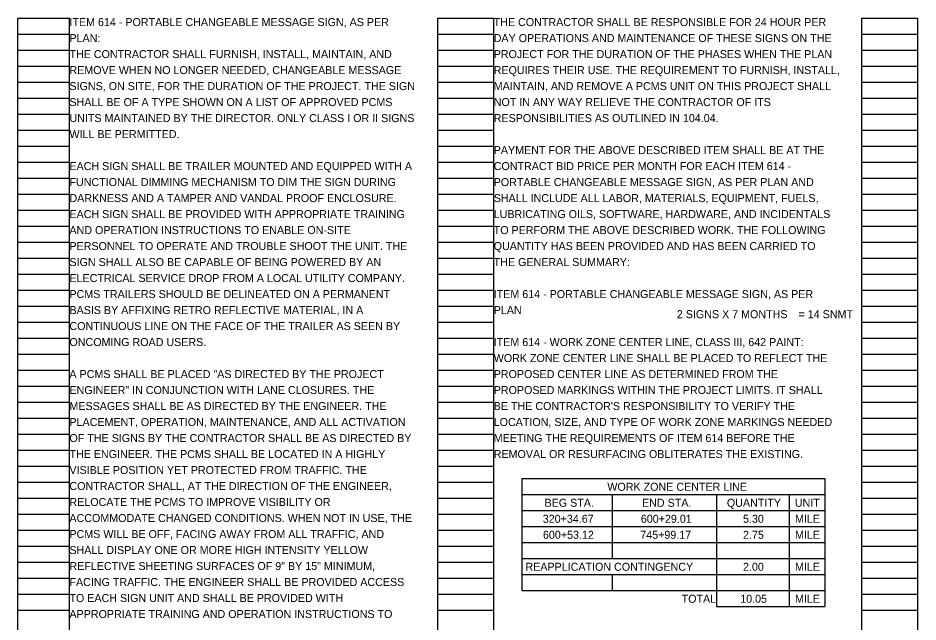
# Model space of a CAD drawing. Extents: x 63 to 145.9, y -75 to 21.1.
# Drawn here: x 64.47 to 80.21, y -39.43 to -28.86 of the extents above; entities that cross this region are included whole.
import ezdxf

# ---------------------------------------------------------------- set-up
doc = ezdxf.new("R2010")
doc.units = 0
doc.layers.add('AP_P_Airside', color=7, linetype='Continuous')
doc.layers.add('SH_Text', color=7, linetype='Continuous')

msp = doc.modelspace()

# ---------------------------------------------------------------- linework, layer by layer
at = {"layer": 'AP_P_Airside'}
for p, q in [((73.275, -36.919), (78.579, -36.919)), ((73.275, -36.919), (73.275, -38.879)), ((78.579, -36.919), (78.579, -39.159)), ((73.275, -37.199), (78.579, -37.199)), ((74.856, -37.199), (74.856, -38.319)), ((76.684, -37.199), (76.684, -39.159)), ((77.953, -37.199), (77.953, -39.159)), ((73.275, -37.479), (78.579, -37.479)), ((73.275, -37.759), (78.579, -37.759)), ((73.275, -38.039), (78.579, -38.039)), ((73.275, -38.319), (78.579, -38.319)), ((73.275, -38.599), (78.579, -38.599)), ((74.856, -38.599), (74.856, -38.879)), ((73.275, -38.879), (78.579, -38.879)), ((76.684, -39.159), (78.579, -39.159))]:
    msp.add_line(p, q, dxfattribs=at)
at = {"layer": 'SH_Text'}
for p, q in [((64.466, -49.02), (64.466, -28.86)), ((64.466, -28.86), (65.366, -28.86)), ((65.366, -49.02), (65.366, -28.86)), ((71.806, -49.02), (71.806, -28.86)), ((71.806, -28.86), (72.786, -28.86)), ((72.786, -49.02), (72.786, -28.86)), ((79.226, -49.02), (79.226, -28.86)), ((79.226, -28.86), (80.206, -28.86)), ((80.206, -49.02), (80.206, -28.86)), ((64.466, -29.14), (65.366, -29.14)), ((71.806, -29.14), (72.786, -29.14)), ((79.226, -29.14), (80.206, -29.14)), ((64.466, -29.42), (65.366, -29.42)), ((71.806, -29.42), (72.786, -29.42)), ((79.226, -29.42), (80.206, -29.42)), ((64.466, -29.7), (65.366, -29.7)), ((71.806, -29.7), (72.786, -29.7)), ((79.226, -29.7), (80.206, -29.7)), ((64.466, -29.98), (65.366, -29.98)), ((71.806, -29.98), (72.786, -29.98)), ((79.226, -29.98), (80.206, -29.98)), ((64.466, -30.26), (65.366, -30.26)), ((71.806, -30.26), (72.786, -30.26)), ((79.226, -30.26), (80.206, -30.26)), ((64.466, -30.54), (65.366, -30.54)), ((71.806, -30.54), (72.786, -30.54)), ((79.226, -30.54), (80.206, -30.54)), ((64.466, -30.82), (65.366, -30.82)), ((71.806, -30.82), (72.786, -30.82)), ((79.226, -30.82), (80.206, -30.82)), ((64.466, -31.1), (65.366, -31.1)), ((71.806, -31.1), (72.786, -31.1)), ((79.226, -31.1), (80.206, -31.1)), ((64.466, -31.38), (65.366, -31.38)), ((71.806, -31.38), (72.786, -31.38)), ((79.226, -31.38), (80.206, -31.38)), ((64.466, -31.66), (65.366, -31.66)), ((71.806, -31.66), (72.786, -31.66)), ((79.226, -31.66), (80.206, -31.66)), ((64.466, -31.94), (65.366, -31.94)), ((71.806, -31.94), (72.786, -31.94)), ((79.226, -31.94), (80.206, -31.94)), ((64.466, -32.22), (65.366, -32.22)), ((71.806, -32.22), (72.786, -32.22)), ((79.226, -32.22), (80.206, -32.22)), ((64.466, -32.5), (65.366, -32.5)), ((71.806, -32.5), (72.786, -32.5)), ((79.226, -32.5), (80.206, -32.5)), ((64.466, -32.78), (65.366, -32.78)), ((71.806, -32.78), (72.786, -32.78)), ((79.226, -32.78), (80.206, -32.78)), ((64.466, -33.06), (65.366, -33.06)), ((71.806, -33.06), (72.786, -33.06)), ((79.226, -33.06), (80.206, -33.06)), ((64.466, -33.34), (65.366, -33.34)), ((71.806, -33.34), (72.786, -33.34)), ((79.226, -33.34), (80.206, -33.34)), ((64.466, -33.62), (65.366, -33.62)), ((71.806, -33.62), (72.786, -33.62)), ((79.226, -33.62), (80.206, -33.62)), ((64.466, -33.9), (65.366, -33.9)), ((71.806, -33.9), (72.786, -33.9)), ((79.226, -33.9), (80.206, -33.9)), ((64.466, -34.18), (65.366, -34.18)), ((71.806, -34.18), (72.786, -34.18)), ((79.226, -34.18), (80.206, -34.18)), ((64.466, -34.46), (65.366, -34.46)), ((71.806, -34.46), (72.786, -34.46)), ((79.226, -34.46), (80.206, -34.46)), ((64.466, -34.74), (65.366, -34.74)), ((71.806, -34.74), (72.786, -34.74)), ((79.226, -34.74), (80.206, -34.74)), ((64.466, -35.02), (65.366, -35.02)), ((71.806, -35.02), (72.786, -35.02)), ((79.226, -35.02), (80.206, -35.02)), ((64.466, -35.3), (65.366, -35.3)), ((71.806, -35.3), (72.786, -35.3)), ((79.226, -35.3), (80.206, -35.3)), ((64.466, -35.58), (65.366, -35.58)), ((71.806, -35.58), (72.786, -35.58)), ((79.226, -35.58), (80.206, -35.58)), ((64.466, -35.86), (65.366, -35.86)), ((71.806, -35.86), (72.786, -35.86)), ((79.226, -35.86), (80.206, -35.86)), ((64.466, -36.14), (65.366, -36.14)), ((71.806, -36.14), (72.786, -36.14)), ((79.226, -36.14), (80.206, -36.14)), ((64.466, -36.42), (65.366, -36.42)), ((71.806, -36.42), (72.786, -36.42)), ((79.226, -36.42), (80.206, -36.42)), ((64.466, -36.7), (65.366, -36.7)), ((71.806, -36.7), (72.786, -36.7)), ((79.226, -36.7), (80.206, -36.7)), ((64.466, -36.98), (65.366, -36.98)), ((71.806, -36.98), (72.786, -36.98)), ((79.226, -36.98), (80.206, -36.98)), ((64.466, -37.26), (65.366, -37.26)), ((71.806, -37.26), (72.786, -37.26)), ((79.226, -37.26), (80.206, -37.26)), ((64.466, -37.54), (65.366, -37.54)), ((71.806, -37.54), (72.786, -37.54)), ((79.226, -37.54), (80.206, -37.54)), ((64.466, -37.82), (65.366, -37.82)), ((71.806, -37.82), (72.786, -37.82)), ((79.226, -37.82), (80.206, -37.82)), ((64.466, -38.1), (65.366, -38.1)), ((71.806, -38.1), (72.786, -38.1)), ((79.226, -38.1), (80.206, -38.1)), ((64.466, -38.38), (65.366, -38.38)), ((71.806, -38.38), (72.786, -38.38)), ((79.226, -38.38), (80.206, -38.38)), ((64.466, -38.66), (65.366, -38.66)), ((71.806, -38.66), (72.786, -38.66)), ((79.226, -38.66), (80.206, -38.66)), ((64.466, -38.94), (65.366, -38.94)), ((71.806, -38.94), (72.786, -38.94)), ((79.226, -38.94), (80.206, -38.94)), ((64.466, -39.22), (65.366, -39.22)), ((71.806, -39.22), (72.786, -39.22)), ((79.226, -39.22), (80.206, -39.22))]:
    msp.add_line(p, q, dxfattribs=at)

# ---------------------------------------------------------------- texts
at = {"layer": 'AP_P_Airside'}
for s, p in [('ITEM 614 - PORTABLE CHANGEABLE MESSAGE SIGN, AS PER ', (65.366, -29)), ('THE CONTRACTOR SHALL BE RESPONSIBLE FOR 24 HOUR PER ', (72.786, -29)), ('PLAN:', (65.366, -29.28)), ('DAY OPERATIONS AND MAINTENANCE OF THESE SIGNS ON THE ', (72.786, -29.28)), ('THE CONTRACTOR SHALL FURNISH, INSTALL, MAINTAIN, AND ', (65.366, -29.56)), ('PROJECT FOR THE DURATION OF THE PHASES WHEN THE PLAN ', (72.786, -29.56)), ('REMOVE WHEN NO LONGER NEEDED, CHANGEABLE MESSAGE ', (65.366, -29.84)), ('REQUIRES THEIR USE. THE REQUIREMENT TO FURNISH, INSTALL, ', (72.786, -29.84)), ('SIGNS, ON SITE, FOR THE DURATION OF THE PROJECT. THE SIGN ', (65.366, -30.12)), ('MAINTAIN, AND REMOVE A PCMS UNIT ON THIS PROJECT SHALL ', (72.786, -30.12)), ('SHALL BE OF A TYPE SHOWN ON A LIST OF APPROVED PCMS ', (65.366, -30.4)), ('NOT IN ANY WAY RELIEVE THE CONTRACTOR OF ITS ', (72.786, -30.4)), ('UNITS MAINTAINED BY THE DIRECTOR. ONLY CLASS I OR II SIGNS ', (65.366, -30.68)), ('RESPONSIBILITIES AS OUTLINED IN 104.04.', (72.786, -30.68)), ('WILL BE PERMITTED.', (65.366, -30.96)), ('PAYMENT FOR THE ABOVE DESCRIBED ITEM SHALL BE AT THE ', (72.786, -31.24)), ('EACH SIGN SHALL BE TRAILER MOUNTED AND EQUIPPED WITH A ', (65.366, -31.52)), ('CONTRACT BID PRICE PER MONTH FOR EACH ITEM 614 - ', (72.786, -31.52)), ('FUNCTIONAL DIMMING MECHANISM TO DIM THE SIGN DURING ', (65.366, -31.8)), ('PORTABLE CHANGEABLE MESSAGE SIGN, AS PER PLAN AND ', (72.786, -31.8)), ('DARKNESS AND A TAMPER AND VANDAL PROOF ENCLOSURE. ', (65.366, -32.08)), ('SHALL INCLUDE ALL LABOR, MATERIALS, EQUIPMENT, FUELS, ', (72.786, -32.08)), ('EACH SIGN SHALL BE PROVIDED WITH APPROPRIATE TRAINING ', (65.366, -32.36)), ('LUBRICATING OILS, SOFTWARE, HARDWARE, AND INCIDENTALS ', (72.786, -32.36)), ('AND OPERATION INSTRUCTIONS TO ENABLE ON-SITE ', (65.366, -32.64)), ('TO PERFORM THE ABOVE DESCRIBED WORK. THE FOLLOWING ', (72.786, -32.64)), ('PERSONNEL TO OPERATE AND TROUBLE SHOOT THE UNIT. THE ', (65.366, -32.92)), ('QUANTITY HAS BEEN PROVIDED AND HAS BEEN CARRIED TO ', (72.786, -32.92)), ('SIGN SHALL ALSO BE CAPABLE OF BEING POWERED BY AN ', (65.366, -33.2)), ('THE GENERAL SUMMARY:', (72.786, -33.2)), ('ELECTRICAL SERVICE DROP FROM A LOCAL UTILITY COMPANY. ', (65.366, -33.48)), ('PCMS TRAILERS SHOULD BE DELINEATED ON A PERMANENT ', (65.366, -33.76)), ('ITEM 614 - PORTABLE CHANGEABLE MESSAGE SIGN, AS PER ', (72.786, -33.76)), ('BASIS BY AFFIXING RETRO REFLECTIVE MATERIAL, IN A ', (65.366, -34.04)), ('PLAN', (72.786, -34.04)), ('2 SIGNS X 7 MONTHS', (75.989, -34.112)), ('= 14 SNMT', (78.117, -34.112)), ('CONTINUOUS LINE ON THE FACE OF THE TRAILER AS SEEN BY ', (65.366, -34.32)), ('ONCOMING ROAD USERS.', (65.366, -34.6)), ('ITEM 614 - WORK ZONE CENTER LINE, CLASS III, 642 PAINT:', (72.786, -34.6)), ('WORK ZONE CENTER LINE SHALL BE PLACED TO REFLECT THE ', (72.786, -34.88)), ('A PCMS SHALL BE PLACED "AS DIRECTED BY THE PROJECT ', (65.366, -35.16)), ('PROPOSED CENTER LINE AS DETERMINED FROM THE ', (72.786, -35.16)), ('ENGINEER" IN CONJUNCTION WITH LANE CLOSURES. THE ', (65.366, -35.44)), ('PROPOSED MARKINGS WITHIN THE PROJECT LIMITS. IT SHALL ', (72.786, -35.44)), ('MESSAGES SHALL BE AS DIRECTED BY THE ENGINEER. THE ', (65.366, -35.72)), ("BE THE CONTRACTOR'S RESPONSIBILITY TO VERIFY THE ", (72.786, -35.72)), ('PLACEMENT, OPERATION, MAINTENANCE, AND ALL ACTIVATION ', (65.366, -36)), ('LOCATION, SIZE, AND TYPE OF WORK ZONE MARKINGS NEEDED ', (72.786, -36)), ('OF THE SIGNS BY THE CONTRACTOR SHALL BE AS DIRECTED BY ', (65.366, -36.28)), ('MEETING THE REQUIREMENTS OF ITEM 614 BEFORE THE ', (72.786, -36.28)), ('THE ENGINEER. THE PCMS SHALL BE LOCATED IN A HIGHLY ', (65.366, -36.56)), ('REMOVAL OR RESURFACING OBLITERATES THE EXISTING.', (72.786, -36.56)), ('VISIBLE POSITION YET PROTECTED FROM TRAFFIC. THE ', (65.366, -36.84)), ('CONTRACTOR SHALL, AT THE DIRECTION OF THE ENGINEER, ', (65.366, -37.12)), ('WORK ZONE CENTER LINE', (74.773, -37.133)), ('RELOCATE THE PCMS TO IMPROVE VISIBILITY OR ', (65.366, -37.4)), ('BEG STA.', (73.675, -37.413)), ('END STA.', (75.38, -37.413)), ('QUANTITY', (76.864, -37.413)), ('UNIT', (78.052, -37.413)), ('ACCOMMODATE CHANGED CONDITIONS. WHEN NOT IN USE, THE ', (65.366, -37.68)), ('320+34.67', (73.644, -37.693)), ('600+29.01', (75.359, -37.693)), ('5.30', (77.146, -37.693)), ('MILE', (78.056, -37.693)), ('PCMS WILL BE OFF, FACING AWAY FROM ALL TRAFFIC, AND ', (65.366, -37.96)), ('600+53.12', (73.647, -37.973)), ('745+99.17', (75.349, -37.973)), ('2.75', (77.146, -37.973)), ('MILE', (78.056, -37.973)), ('SHALL DISPLAY ONE OR MORE HIGH INTENSITY YELLOW ', (65.366, -38.24)), ('REFLECTIVE SHEETING SURFACES OF 9" BY 15" MINIMUM, ', (65.366, -38.52)), ('REAPPLICATION CONTINGENCY', (73.341, -38.533)), ('2.00', (77.146, -38.533)), ('MILE', (78.056, -38.533)), ('FACING TRAFFIC. THE ENGINEER SHALL BE PROVIDED ACCESS ', (65.366, -38.8)), ('TO EACH SIGN UNIT AND SHALL BE PROVIDED WITH ', (65.366, -39.08)), ('TOTAL', (76.073, -39.093)), ('10.05', (77.097, -39.093)), ('MILE', (78.056, -39.093)), ('APPROPRIATE TRAINING AND OPERATION INSTRUCTIONS TO ', (65.366, -39.36))]:
    msp.add_text(s, height=0.14, dxfattribs=at).set_placement(p)

doc.saveas('drawing.dxf')
